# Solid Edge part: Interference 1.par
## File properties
Last saved by: Lee
Revision: 59
Accuracy: 0.990
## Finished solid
Body 1: solid body, 4 faces, 4 edges, 0 vertices.
  Faces by surface: cylinder 4
  Edges by curve: intersection 4
Body 2: solid body, 4 faces, 4 edges, 2 vertices.
  Faces by surface: cylinder 3, plane 1
  Edges by curve: intersection 2, circle 1, ellipse 1
Body 3: solid body, 5 faces, 6 edges, 2 vertices.
  Faces by surface: cylinder 4, plane 1
  Edges by curve: intersection 4, circle 1, ellipse 1
Body 4: solid body, 5 faces, 7 edges, 4 vertices.
  Faces by surface: cylinder 4, plane 1
  Edges by curve: intersection 3, circle 2, ellipse 2
Body 5: solid body, 4 faces, 4 edges, 0 vertices.
  Faces by surface: cylinder 4
  Edges by curve: intersection 4
Body 6: solid body, 6 faces, 12 edges, 8 vertices.
  Faces by surface: cylinder 4, plane 2
  Edges by curve: circle 4, ellipse 4, intersection 4
Body 7: solid body, 4 faces, 4 edges, 0 vertices.
  Faces by surface: cylinder 4
  Edges by curve: intersection 4
Body 8: solid body, 6 faces, 12 edges, 8 vertices.
  Faces by surface: cylinder 4, plane 2
  Edges by curve: circle 4, ellipse 4, intersection 4
Bounding box of the edges (mm): 1721.306 x 769.077 x 416.565, from (-809.8158, -383.5364, 214.5211) to (911.4903, 385.5402, 631.0857).
Cylindrical faces by radius (mm): R5 x1, R37 x4, R38.5 x2, R91 x4, R109.5375 x4, R850 x8, R875.4 x8
Planar faces by outward normal: oblique 7
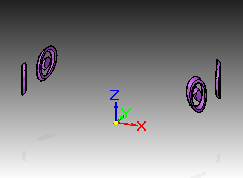
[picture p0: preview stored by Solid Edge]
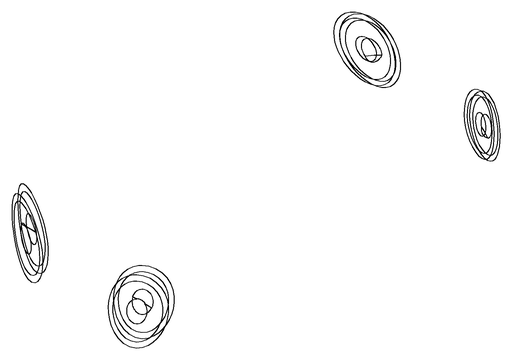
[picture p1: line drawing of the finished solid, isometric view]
